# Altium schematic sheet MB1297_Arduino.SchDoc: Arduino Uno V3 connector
size A4; Date: Not used; ApprovedBy: Not used; CheckedBy: Not used; Author: Not used; CompanyName: STMicroelectronics; DrawnBy: Not used; Engineer: Not used; Organization: Not used; Address1: Not used; Address2: Not used; Address3: Not used; Address4: Not used; DocumentNumber: Not used; Revision: Not used; SheetNumber: 10; SheetTotal: 12
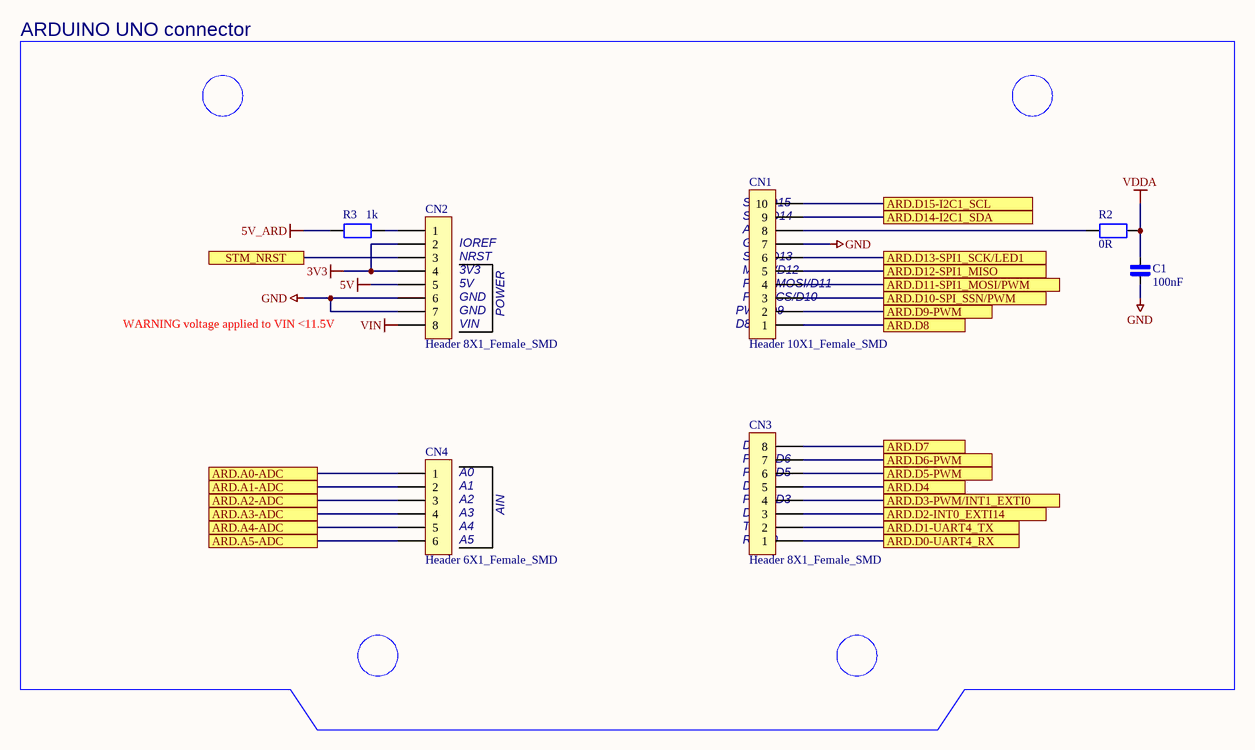
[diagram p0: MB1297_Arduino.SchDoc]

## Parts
C1  100nF  [0402]
CN1  Header 10X1_Female_SMD  [F-V50XC-1X10R-LF]
CN2  Header 8X1_Female_SMD  [F-V50XC-1X08R-LF]
CN3  Header 8X1_Female_SMD  [F-V50XC-1X08R-LF]
CN4  Header 6X1_Female_SMD  [F-V50XC-1X06R-LF]
R2  0R  [0402]
R3  1k  [0402]

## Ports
ARD.A0-ADC, ARD.A1-ADC, ARD.A2-ADC, ARD.A3-ADC, ARD.A4-ADC, ARD.A5-ADC, ARD.D0-UART4_RX, ARD.D1-UART4_TX, ARD.D2-INT0_EXTI14, ARD.D3-PWM/INT1_EXTI0, ARD.D4, ARD.D5-PWM, ARD.D6-PWM, ARD.D7, ARD.D8, ARD.D9-PWM, ARD.D10-SPI_SSN/PWM, ARD.D11-SPI1_MOSI/PWM, ARD.D12-SPI1_MISO, ARD.D13-SPI1_SCK/LED1, ARD.D14-I2C1_SDA, ARD.D15-I2C1_SCL, STM_NRST

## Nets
3V3: CN2.2 CN2.4
5V: CN2.5
5V_ARD: R3.1
GND: C1.2 CN1.7 CN2.6 CN2.7
VDDA: C1.1 R2.2
VIN: CN2.8
ARD.A0-ADC: CN4.1 ; port ARD.A0-ADC
ARD.A1-ADC: CN4.2 ; port ARD.A1-ADC
ARD.A2-ADC: CN4.3 ; port ARD.A2-ADC
ARD.A3-ADC: CN4.4 ; port ARD.A3-ADC
ARD.A4-ADC: CN4.5 ; port ARD.A4-ADC
ARD.A5-ADC: CN4.6 ; port ARD.A5-ADC
ARD.D0-UART4_RX: CN3.1 ; port ARD.D0-UART4_RX
ARD.D1-UART4_TX: CN3.2 ; port ARD.D1-UART4_TX
ARD.D2-INT0_EXTI14: CN3.3 ; port ARD.D2-INT0_EXTI14
ARD.D3-PWM/INT1_EXTI0: CN3.4 ; port ARD.D3-PWM/INT1_EXTI0
ARD.D4: CN3.5 ; port ARD.D4
ARD.D5-PWM: CN3.6 ; port ARD.D5-PWM
ARD.D6-PWM: CN3.7 ; port ARD.D6-PWM
ARD.D7: CN3.8 ; port ARD.D7
ARD.D8: CN1.1 ; port ARD.D8
ARD.D9-PWM: CN1.2 ; port ARD.D9-PWM
ARD.D10-SPI_SSN/PWM: CN1.3 ; port ARD.D10-SPI_SSN/PWM
ARD.D11-SPI1_MOSI/PWM: CN1.4 ; port ARD.D11-SPI1_MOSI/PWM
ARD.D12-SPI1_MISO: CN1.5 ; port ARD.D12-SPI1_MISO
ARD.D13-SPI1_SCK/LED1: CN1.6 ; port ARD.D13-SPI1_SCK/LED1
ARD.D14-I2C1_SDA: CN1.9 ; port ARD.D14-I2C1_SDA
ARD.D15-I2C1_SCL: CN1.10 ; port ARD.D15-I2C1_SCL
STM_NRST: CN2.3 ; port STM_NRST
NetCN1_8: CN1.8 R2.1
NetCN2_1: CN2.1 R3.2

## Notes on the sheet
- ARDUINO UNO connector
- (near CN1) SCL/D15
- (near CN2) IOREF
- (near CN2) NRST
- (near CN2) 3V3
- (near CN2) 5V
- (near CN1) SDA/D14
- (near CN1) SCK/D13
- (near CN1) MISO/D12
- (near CN1) PWM/MOSI/D11
- (near CN1) AVDD
- (near CN1) GND
- WARNING voltage applied to VIN <11.5V
- (near CN2) GND
- (near CN2) VIN
- POWER
- (near CN1) D8
- (near CN1) PWM/D9
- (near CN1) PWM/CS/D10
- (near CN4) A0
- (near CN3) PWM/D5
- (near CN3) PWM/D6
- (near CN3) D7
- (near CN4) A1
- (near CN4) A2
- (near CN4) A3
- (near CN4) A4
- (near CN4) A5
- AIN
- (near CN3) RX/D0
- (near CN3) TX/D1
- (near CN3) D2
- (near CN3) D4
- (near CN3) PWM/D3

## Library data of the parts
C1 = CAP_NPOL: Capacitor_not polarized
CN1 = Header 10X1_Female_SMD: Header, 10-Pin, SMD, Single row,female
CN2 CN3 = Header 8X1_Female_SMD: Header, 8-Pin, SMD, Single row,female
CN4 = Header 6X1_Female_SMD: Header, 6-Pin, SMD, Single row,female
R2 R3 = RES: Resistor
